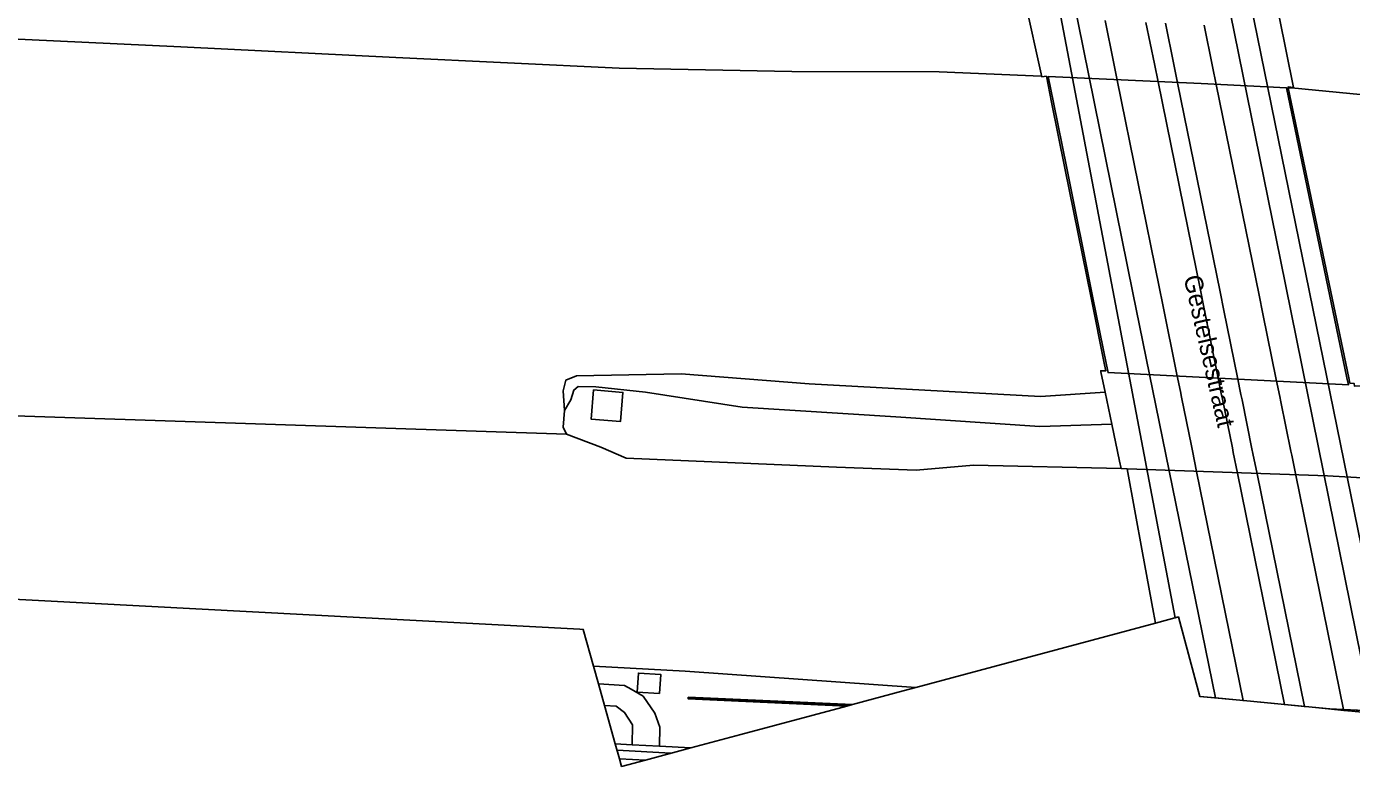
# Model space of a CAD drawing. Extents: x 160203 to 161530, y 379528 to 381797.
# Drawn here: x 160921.4 to 160995.1, y 379565.8 to 379606.9 of the extents above; entities that cross this region are included whole.
import ezdxf

# ---------------------------------------------------------------- set-up
doc = ezdxf.new("R2010")
doc.units = 0
for name, color, linetype in [('IMGEO_Berm_groen', 7, 'Continuous'), ('IMGEO_Berm_open', 7, 'Continuous'), ('IMGEO_Geluidsscherm', 7, 'Continuous'), ('IMGEO_Muur', 7, 'Continuous'), ('IMGEO_Openbare_ruimte_label', 7, 'Continuous'), ('IMGEO_Rijbaan_autosnelweg', 7, 'Continuous'), ('IMGEO_Rijbaan_autoweg', 7, 'Continuous'), ('IMGEO_Rijbaan_lokaal_gesloten', 7, 'Continuous'), ('IMGEO_Rijbaan_lokaal_open', 7, 'Continuous'), ('IMGEO_Terreindeel_gesloten', 7, 'Continuous')]:
    doc.layers.add(name, color=color, linetype=linetype)

msp = doc.modelspace()

# ---------------------------------------------------------------- linework, layer by layer
at = {"layer": 'IMGEO_Berm_groen'}
msp.add_lwpolyline([(160917.823, 379606.36), (160930.026, 379605.796), (160941.962, 379605.2), (160954.373, 379604.607), (160963.966, 379604.433), (160972.149, 379604.403), (160977.823, 379604.174), (160977.866, 379604.134), (160976.912, 379608.392), (160976.637, 379608.633), (160967.962, 379609.047), (160964.136, 379609.345), (160957.759, 379609.99), (160948.003, 379610.444), (160930.12, 379611.255), (160916.76, 379611.92)], dxfattribs=at)
for points in [[(161053.636, 379605.215), (161034.405, 379606.14), (161020.393, 379606.728), (161003.46, 379607.335), (160996.432, 379607.547), (160991.039, 379607.484), (160991.843, 379603.531), (160991.537, 379603.567), (160991.548, 379603.518), (160991.737, 379603.509), (161001.45, 379602.58), (161008.243, 379601.966), (161012.988, 379601.702), (161022.774, 379601.217), (161028.674, 379600.968), (161038.149, 379600.483), (161048.083, 379600.029)], [(160951.335, 379585.602), (160951.689, 379586.196), (160951.865, 379586.731), (160952.101, 379586.939), (160953.08, 379586.913), (160955.838, 379586.626), (160961.208, 379585.785), (160969.749, 379585.252), (160977.757, 379584.717), (160981.752, 379584.841), (160981.378, 379586.619), (160977.78, 379586.378), (160964.939, 379587.074), (160957.821, 379587.641), (160952.01, 379587.532), (160951.418, 379587.293), (160951.272, 379586.699)], [(160981.752, 379584.841), (160977.757, 379584.717), (160969.749, 379585.252), (160961.208, 379585.785), (160955.838, 379586.626), (160953.08, 379586.913), (160952.101, 379586.939), (160951.865, 379586.731), (160951.689, 379586.196), (160951.335, 379585.602), (160951.266, 379584.681), (160951.454, 379584.282), (160953.349, 379583.567), (160954.764, 379582.958), (160966.448, 379582.451), (160970.881, 379582.289), (160974.068, 379582.567), (160982.27, 379582.376), (160982.183, 379582.789)], [(160952.957, 379586.746), (160954.58, 379586.608), (160954.441, 379584.989), (160952.819, 379585.128)], [(160967.023, 379569.194), (160958.212, 379569.583), (160958.216, 379569.683), (160967.344, 379569.28), (160970.147, 379570.032), (160970.851, 379570.221), (160958.035, 379571.124), (160952.953, 379571.397), (160953.226, 379570.42), (160954.665, 379570.336), (160955.039, 379570.138), (160955.707, 379569.745), (160956.351, 379568.804), (160956.639, 379568.022), (160956.619, 379566.958), (160958.358, 379566.868), (160961.129, 379567.612)], [(160953.226, 379570.42), (160953.562, 379569.222), (160954.215, 379569.188), (160954.678, 379568.834), (160955.108, 379568.142), (160955.099, 379567.037), (160956.619, 379566.958), (160956.639, 379568.022), (160956.351, 379568.804), (160955.707, 379569.745), (160955.039, 379570.138), (160954.665, 379570.336)], [(160956.622, 379569.886), (160955.373, 379569.971), (160955.443, 379571.021), (160956.692, 379570.937)], [(160954.16, 379567.085), (160955.099, 379567.037), (160955.108, 379568.142), (160954.678, 379568.834), (160954.215, 379569.188), (160953.562, 379569.222)], [(160955.834, 379566.191), (160954.51, 379565.836), (160954.39, 379566.263)]]:
    msp.add_lwpolyline(points, close=True, dxfattribs=at)
at = {"layer": 'IMGEO_Berm_open'}
for points in [[(160986.87, 379607.001), (160987.338, 379604.708), (160987.543, 379603.7), (160989.929, 379592.011), (160990.143, 379590.961), (160990.886, 379587.322), (160991.076, 379586.388), (160991.138, 379586.085), (160991.696, 379583.351), (160991.743, 379583.123), (160991.971, 379582.005), (160994.626, 379568.994), (160996.203, 379568.92), (160991.115, 379593.962), (160986.011, 379619.113)], [(160983.646, 379607.151), (160984.112, 379604.856), (160984.317, 379603.848), (160986.666, 379592.283), (160986.874, 379591.255), (160987.64, 379587.488), (160987.831, 379586.544), (160987.894, 379586.236), (160988.445, 379583.524), (160988.497, 379583.264), (160988.728, 379582.129), (160991.339, 379569.271), (160992.449, 379569.164), (160989.817, 379582.087), (160989.587, 379583.217), (160989.536, 379583.466), (160988.983, 379586.185), (160988.92, 379586.491), (160988.729, 379587.432), (160987.97, 379591.156), (160987.759, 379592.191), (160985.396, 379603.798), (160985.19, 379604.806), (160984.723, 379607.101)]]:
    msp.add_lwpolyline(points, dxfattribs=at)
msp.add_lwpolyline([(160996.228, 379568.799), (160996.203, 379568.92), (160994.626, 379568.994), (160994.638, 379568.952), (160995.074, 379568.91), (160996.04, 379568.817)], close=True, dxfattribs=at)
at = {"layer": 'IMGEO_Geluidsscherm'}
for points in [[(160967.184, 379569.237), (160958.214, 379569.633)], [(160954.255, 379566.746), (160957.237, 379566.568)]]:
    msp.add_lwpolyline(points, dxfattribs=at)
at = {"layer": 'IMGEO_Muur'}
for points in [[(160967.023, 379569.194), (160967.344, 379569.28), (160958.216, 379569.683), (160958.212, 379569.583)], [(160955.834, 379566.191), (160954.39, 379566.263), (160954.16, 379567.085), (160955.099, 379567.037), (160956.619, 379566.958), (160958.358, 379566.868)]]:
    msp.add_lwpolyline(points, close=True, dxfattribs=at)
at = {"layer": 'IMGEO_Rijbaan_autosnelweg'}
msp.add_lwpolyline([(160907.388, 379585.75), (160951.454, 379584.282), (160951.266, 379584.681), (160951.335, 379585.602), (160951.272, 379586.699), (160951.418, 379587.293), (160952.01, 379587.532), (160957.821, 379587.641), (160964.939, 379587.074), (160977.78, 379586.378), (160981.378, 379586.619), (160981.139, 379587.757), (160981.129, 379587.807), (160981.416, 379587.805), (160981.349, 379588.135), (160980.597, 379591.855), (160979.141, 379599.063), (160978.402, 379602.717), (160978.111, 379604.157), (160977.866, 379604.134), (160977.823, 379604.174), (160972.149, 379604.403), (160963.966, 379604.433), (160954.373, 379604.607), (160941.962, 379605.2), (160930.026, 379605.796), (160917.823, 379606.36)], dxfattribs=at)
for points in [[(160978.214, 379604.156), (160978.505, 379602.712), (160979.244, 379599.058), (160980.701, 379591.849), (160981.451, 379588.132), (160981.538, 379587.704), (160994.892, 379587.021), (160994.809, 379587.417), (160991.444, 379603.523), (160986.71, 379603.758)], [(160991.548, 379603.518), (160994.912, 379587.411), (160994.974, 379587.116), (160995.206, 379587.102), (160995.237, 379586.951), (161001.242, 379587.148), (161014.202, 379586.468), (161029.386, 379585.706), (161040.587, 379588.891), (161039.466, 379592.573), (161042.657, 379595.935), (161048.547, 379599.263), (161048.083, 379600.029), (161038.149, 379600.483), (161028.674, 379600.968), (161022.774, 379601.217), (161012.988, 379601.702), (161008.243, 379601.966), (161001.45, 379602.58), (160991.737, 379603.509)]]:
    msp.add_lwpolyline(points, close=True, dxfattribs=at)
at = {"layer": 'IMGEO_Rijbaan_autoweg'}
msp.add_lwpolyline([(160870.69, 379577.779), (160952.193, 379573.459), (160952.378, 379573.449), (160952.953, 379571.397), (160958.035, 379571.124), (160970.851, 379570.221), (160984.166, 379573.794), (160984.057, 379574.389), (160983.453, 379577.692), (160982.598, 379582.36), (160982.27, 379582.376), (160974.068, 379582.567), (160970.881, 379582.289), (160966.448, 379582.451), (160954.764, 379582.958), (160953.349, 379583.567), (160951.454, 379584.282), (160907.388, 379585.75)], dxfattribs=at)
msp.add_lwpolyline([(160993.854, 379569.028), (160997.895, 379568.84), (160998.721, 379568.789), (160998.669, 379569.039), (160998.386, 379570.389), (160997.694, 379573.698), (160996.998, 379577.025), (160995.99, 379581.846), (160993.725, 379581.972), (160982.598, 379582.36), (160983.453, 379577.692), (160984.057, 379574.389), (160984.166, 379573.794), (160985.451, 379574.139), (160986.637, 379569.726), (160989.064, 379569.491), (160992.688, 379569.141)], close=True, dxfattribs=at)
at = {"layer": 'IMGEO_Rijbaan_lokaal_gesloten'}
for points in [[(160981.375, 379607.257), (160981.842, 379604.959), (160982.046, 379603.951), (160984.377, 379592.473), (160984.582, 379591.462), (160985.365, 379587.604), (160985.558, 379586.652), (160985.622, 379586.342), (160986.169, 379583.645), (160986.226, 379583.363), (160986.459, 379582.216), (160989.042, 379569.493), (160989.064, 379569.491), (160991.339, 379569.271), (160988.728, 379582.129), (160988.497, 379583.264), (160988.445, 379583.524), (160987.894, 379586.236), (160987.831, 379586.544), (160987.64, 379587.488), (160986.874, 379591.255), (160986.666, 379592.283), (160984.317, 379603.848), (160984.112, 379604.856), (160983.646, 379607.151)], [(160984.723, 379607.101), (160985.19, 379604.806), (160985.396, 379603.798), (160987.759, 379592.191), (160987.97, 379591.156), (160988.729, 379587.432), (160988.92, 379586.491), (160988.983, 379586.185), (160989.536, 379583.466), (160989.587, 379583.217), (160989.817, 379582.087), (160992.449, 379569.164), (160992.688, 379569.141), (160993.788, 379569.034), (160994.206, 379569.015), (160994.626, 379568.994), (160991.971, 379582.005), (160991.743, 379583.123), (160991.696, 379583.351), (160991.138, 379586.085), (160991.076, 379586.388), (160990.886, 379587.322), (160990.143, 379590.961), (160989.929, 379592.011), (160987.543, 379603.7), (160987.338, 379604.708), (160986.87, 379607.001)]]:
    msp.add_lwpolyline(points, dxfattribs=at)
at = {"layer": 'IMGEO_Rijbaan_lokaal_open'}
for points in [[(160977.725, 379617.744), (160982.912, 379592.13), (160987.499, 379569.643), (160989.042, 379569.493), (160986.459, 379582.216), (160986.226, 379583.363), (160986.169, 379583.645), (160985.622, 379586.342), (160985.558, 379586.652), (160985.365, 379587.604), (160984.582, 379591.462), (160984.377, 379592.473), (160982.046, 379603.951), (160981.842, 379604.959), (160981.375, 379607.257)], [(160994.638, 379568.952), (160994.626, 379568.994), (160994.206, 379569.015), (160993.788, 379569.034), (160994.638, 379568.952)]]:
    msp.add_lwpolyline(points, dxfattribs=at)
at = {"layer": 'IMGEO_Terreindeel_gesloten'}
for points in [[(160985.276, 379574.092), (160985.451, 379574.139), (160986.637, 379569.726), (160987.499, 379569.643), (160982.912, 379592.13), (160977.725, 379617.744), (160972.366, 379644.208), (160971.855, 379644.558)], [(160997.536, 379568.672), (160982.153, 379644.021), (160982.142, 379644.022), (160980.878, 379644.084), (160980.901, 379643.971), (160986.011, 379619.113), (160991.115, 379593.962), (160996.203, 379568.92), (160996.228, 379568.799)], [(160952.957, 379586.746), (160952.819, 379585.128), (160954.441, 379584.989), (160954.58, 379586.608)], [(160956.622, 379569.886), (160956.692, 379570.937), (160955.443, 379571.021), (160955.373, 379569.971)]]:
    msp.add_lwpolyline(points, close=True, dxfattribs=at)

# ---------------------------------------------------------------- texts
at = {"layer": 'IMGEO_Openbare_ruimte_label'}
msp.add_text('Gestelsestraat', height=1, rotation=282.82712, dxfattribs=at).set_placement((160985.729, 379593.004))

doc.saveas('drawing.dxf')
